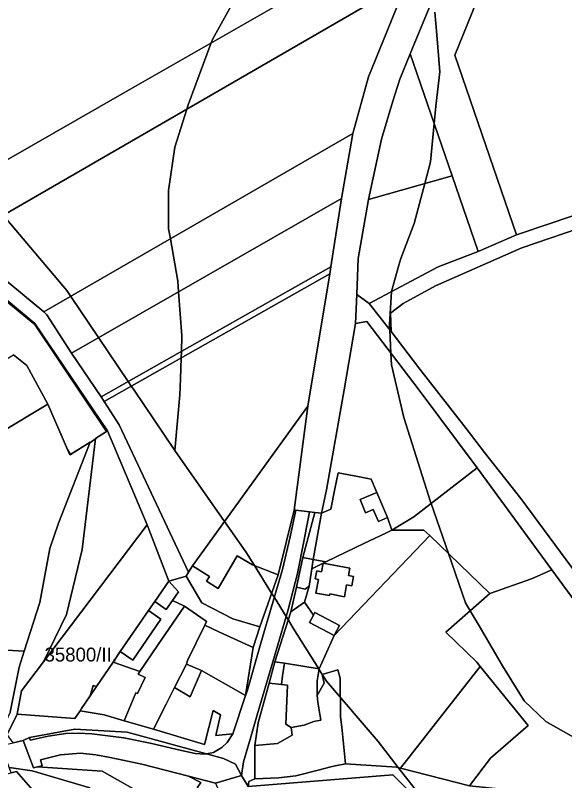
# Model space of a CAD drawing. Extents: x -522079 to -518833, y -1142400 to -1139961.
# Drawn here: x -520469.6 to -520272.1, y -1140796 to -1140520.9 of the extents above; entities that cross this region are included whole.
import ezdxf

# ---------------------------------------------------------------- set-up
doc = ezdxf.new("R2010")
doc.units = 0
for name, color, linetype in [('95560013', 7, 'Continuous'), ('95590013', 7, 'Continuous'), ('95600013', 7, 'Continuous'), ('95610013', 7, 'Continuous'), ('95630013', 7, 'Continuous'), ('95640013', 7, 'Continuous'), ('95660013', 7, 'Continuous')]:
    doc.layers.add(name, color=color, linetype=linetype)

msp = doc.modelspace()

# ---------------------------------------------------------------- linework, layer by layer
at = {"layer": '95560013'}
for points in [[(-520201.76, -1140565.63), (-520263.96, -1140591.19), (-520277.29, -1140595.78), (-520289.45, -1140599.87), (-520311.64, -1140535.23), (-520265.09, -1140420.72), (-520257.35, -1140408.66)], [(-520345.47, -1140414.38), (-520320.44, -1140485.82), (-520431.13, -1140549.18), (-520503.8, -1140590.78), (-520557.7, -1140546.26), (-520562.49, -1140540.48), (-520469.06, -1140486.19)], [(-520490.09, -1140602.11), (-520503.8, -1140590.78), (-520431.13, -1140549.18), (-520320.44, -1140485.82), (-520319.85, -1140487.51), (-520328.73, -1140508.82)], [(-520459.31, -1140627.54), (-520490.09, -1140602.11), (-520328.73, -1140508.82), (-520342.62, -1140543.01), (-520348.21, -1140563.43)], [(-520334.77, -1140627.95), (-520330.21, -1140624.54), (-520318.61, -1140618.22), (-520287.56, -1140604.5), (-520262.2, -1140595.87), (-520167.57, -1140556.99), (-520135.55, -1140594.91), (-520098.36, -1140648.01), (-520267.51, -1140722.14), (-520287.89, -1140694.59), (-520300.9, -1140678.05), (-520307.57, -1140669.43), (-520324.2, -1140648.06), (-520334.5, -1140634.63)], [(-520449.35, -1140642.33), (-520352.4, -1140586.73), (-520356.14, -1140611.39), (-520438.76, -1140658.07)], [(-520356.14, -1140611.39), (-520356.59, -1140613.91), (-520437.69, -1140659.73), (-520438.76, -1140658.07)], [(-520356.59, -1140613.91), (-520364.42, -1140661.36), (-520405.96, -1140718.81), (-520407.37, -1140721.08), (-520432.32, -1140668.06), (-520437.69, -1140659.73)], [(-520303.74, -1140753.44), (-520314.83, -1140742.62), (-520298.98, -1140728.74), (-520284.03, -1140723.41), (-520276.72, -1140720.19), (-520215.27, -1140803.99), (-520216.9, -1140807.42), (-520249.32, -1140803.75), (-520306.3, -1140797.86), (-520298.77, -1140787.91), (-520285.25, -1140776.21), (-520302.54, -1140754.92)]]:
    msp.add_lwpolyline(points, close=True, dxfattribs=at)
at = {"layer": '95590013'}
for points in [[(-520327.66, -1140534.75), (-520312.59, -1140578.66), (-520342.68, -1140587.14), (-520337.95, -1140565.45), (-520333.94, -1140551.84), (-520331.42, -1140543.88)], [(-520449.35, -1140642.33), (-520458.26, -1140628.64), (-520459.31, -1140627.54), (-520348.21, -1140563.43), (-520352.4, -1140586.73)], [(-520342.68, -1140587.14), (-520312.59, -1140578.66), (-520303.27, -1140605.8), (-520317.54, -1140611.38), (-520342.44, -1140624.55), (-520346.89, -1140621.24), (-520346.39, -1140608.35)], [(-520359.48, -1140699.91), (-520357.72, -1140691.49), (-520351.39, -1140655.57), (-520347.36, -1140631.75), (-520343.28, -1140631.04), (-520324.4, -1140655.71), (-520303.56, -1140683.6), (-520326.31, -1140701.14), (-520334.3, -1140706.02), (-520335.84, -1140701.48), (-520339.66, -1140692.44), (-520341.7, -1140687.61), (-520345.87, -1140686.81), (-520353.6, -1140685.32), (-520354.71, -1140691.1), (-520356.12, -1140698.44)], [(-520375.15, -1140722.06), (-520384.29, -1140718.48), (-520389.9, -1140715.22), (-520396.68, -1140726.94), (-520400.9, -1140724.3), (-520399.85, -1140722.62), (-520405.96, -1140718.81), (-520364.42, -1140661.36), (-520369.41, -1140698.76)], [(-520459.41, -1140753.25), (-520451.15, -1140736.24), (-520445.6, -1140712.87), (-520440.71, -1140673.04), (-520436.48, -1140670.33), (-520422.23, -1140704.1)], [(-520276.72, -1140720.19), (-520284.03, -1140723.41), (-520298.98, -1140728.74), (-520320.58, -1140707.95), (-520322.69, -1140705.99), (-520334.3, -1140706.02), (-520326.31, -1140701.14), (-520303.56, -1140683.6)], [(-520445.76, -1140770.03), (-520446.34, -1140770.88), (-520448.2, -1140773.61), (-520468.98, -1140772.14), (-520467.31, -1140763.69), (-520459.41, -1140753.25), (-520422.23, -1140704.1), (-520414.39, -1140724.32), (-520419.44, -1140731.56), (-520421.72, -1140734.81), (-520431.9, -1140749.57), (-520434.44, -1140753.41), (-520440.36, -1140762.11), (-520441.56, -1140761.77), (-520442.66, -1140765.49)], [(-520322.69, -1140705.99), (-520320.58, -1140707.95), (-520354.98, -1140743.86), (-520353.05, -1140740.25), (-520361.88, -1140735.57), (-520362.41, -1140736.49), (-520365.68, -1140731.9), (-520364.02, -1140726.04), (-520363.02, -1140719.82), (-520358.95, -1140717.87), (-520357.97, -1140717.4), (-520347.29, -1140712.26), (-520344.29, -1140710.82), (-520336.43, -1140707.04), (-520334.3, -1140706.02)], [(-520331.09, -1140791.46), (-520332.51, -1140791.1), (-520350.89, -1140789.92), (-520352.17, -1140776.77), (-520352.71, -1140773.02), (-520352.78, -1140759.2), (-520353.64, -1140756.21), (-520359.31, -1140757.88), (-520358.59, -1140760.98), (-520361.04, -1140765.41), (-520361.11, -1140760.14), (-520360.42, -1140755.8), (-520354.98, -1140743.86), (-520320.58, -1140707.95), (-520298.98, -1140728.74), (-520314.83, -1140742.62), (-520303.74, -1140753.44), (-520302.54, -1140754.92)], [(-520358.95, -1140717.87), (-520359.53, -1140720.91), (-520361.21, -1140720.62), (-520361.8, -1140723.5), (-520360.67, -1140723.75), (-520361.57, -1140728.6), (-520356.67, -1140729.48), (-520356.58, -1140728.88), (-520351.32, -1140729.89), (-520350.51, -1140725.65), (-520348.59, -1140726.01), (-520347.97, -1140722.63), (-520349.88, -1140722.27), (-520349.37, -1140719.63)], [(-520302.54, -1140754.92), (-520285.25, -1140776.21), (-520298.77, -1140787.91), (-520306.3, -1140797.86), (-520331.09, -1140791.46)], [(-520375.33, -1140782.59), (-520383.46, -1140783.32), (-520382.29, -1140775.26), (-520378.38, -1140760.91), (-520373.94, -1140761.39), (-520371.72, -1140761.64), (-520372.32, -1140775.75), (-520370.42, -1140776.86), (-520370.11, -1140779.64)]]:
    msp.add_lwpolyline(points, close=True, dxfattribs=at)
at = {"layer": '95600013'}
msp.add_lwpolyline([(-520482.03, -1140698.6), (-520492.24, -1140681.28), (-520457.96, -1140660.67), (-520449.96, -1140678.96), (-520442.74, -1140674.34), (-520454.03, -1140703.46), (-520457.2, -1140712.56), (-520460.77, -1140732), (-520466.36, -1140749.44), (-520479.24, -1140748.79), (-520495.27, -1140747.98), (-520489.4, -1140725.83), (-520488.36, -1140721.89)], close=True, dxfattribs=at)
at = {"layer": '95610013'}
msp.add_lwpolyline([(-520265.09, -1140420.72), (-520311.64, -1140535.23), (-520289.45, -1140599.87), (-520303.27, -1140605.8), (-520312.59, -1140578.66), (-520327.66, -1140534.75), (-520307.77, -1140486.46)], dxfattribs=at)
msp.add_lwpolyline([(-520553.91, -1140708.56), (-520579.53, -1140724.2), (-520579.01, -1140725.05), (-520580.64, -1140725.97), (-520586.97, -1140713.22), (-520470.21, -1140643.01), (-520465.4, -1140646.75), (-520457.96, -1140660.67), (-520492.24, -1140681.28), (-520531.99, -1140705.14), (-520549.51, -1140715.7), (-520553.39, -1140709.41)], close=True, dxfattribs=at)
at = {"layer": '95630013'}
for points in [[(-520560.63, -1140549.81), (-520462.54, -1140631.68), (-520436.48, -1140670.33), (-520440.71, -1140673.04), (-520445.6, -1140712.87), (-520451.15, -1140736.24), (-520459.41, -1140753.25), (-520467.31, -1140763.69), (-520468.98, -1140772.14), (-520472.47, -1140779.4)], [(-520471.47, -1140771.35), (-520468.2, -1140755.18), (-520466.36, -1140749.44), (-520460.77, -1140732), (-520457.2, -1140712.56), (-520454.03, -1140703.46), (-520442.74, -1140674.34), (-520449.96, -1140678.96), (-520457.96, -1140660.67), (-520465.4, -1140646.75), (-520470.21, -1140643.01)], [(-520462.48, -1140800.42), (-520469.2, -1140792.72), (-520471.14, -1140793.15), (-520474.64, -1140783.36), (-520470.41, -1140782.37), (-520466.78, -1140781.53), (-520463.08, -1140791.37), (-520461.64, -1140791.05), (-520438.34, -1140792.64), (-520421.04, -1140802.37)], [(-520397.69, -1140796.9), (-520388.29, -1140794.2), (-520385.85, -1140798.14)], [(-520385.85, -1140798.14), (-520333.88, -1140793.93), (-520323.97, -1140803.87)]]:
    msp.add_lwpolyline(points, dxfattribs=at)
at = {"layer": '95640013'}
for points in [[(-519947.24, -1140466.47), (-520104.66, -1140531.14), (-520155.91, -1140552.2), (-520167.57, -1140556.99), (-520262.2, -1140595.87), (-520287.56, -1140604.5), (-520318.61, -1140618.22), (-520330.21, -1140624.54), (-520334.77, -1140627.95), (-520334.5, -1140634.63), (-520342.44, -1140624.55), (-520317.54, -1140611.38), (-520303.27, -1140605.8), (-520289.45, -1140599.87), (-520277.29, -1140595.78), (-520263.96, -1140591.19), (-520201.76, -1140565.63), (-520182.86, -1140557.87), (-520106.55, -1140526.52), (-520084.71, -1140517.54), (-520041.44, -1140499.76), (-520031.39, -1140495.83), (-519949.02, -1140461.79)], [(-520307.77, -1140486.46), (-520327.66, -1140534.75), (-520331.42, -1140543.88), (-520333.94, -1140551.84), (-520337.95, -1140565.45), (-520342.68, -1140587.14), (-520346.39, -1140608.35), (-520346.89, -1140621.24), (-520347.36, -1140631.75), (-520351.39, -1140655.57), (-520357.72, -1140691.49), (-520359.48, -1140699.91), (-520361.97, -1140699.61), (-520363.79, -1140699.4), (-520368.79, -1140698.83), (-520369.41, -1140698.76), (-520364.42, -1140661.36), (-520356.59, -1140613.91), (-520356.14, -1140611.39), (-520352.4, -1140586.73), (-520348.21, -1140563.43), (-520342.62, -1140543.01), (-520328.73, -1140508.82)], [(-520587.65, -1140510.13), (-520562.49, -1140540.48), (-520557.7, -1140546.26), (-520503.8, -1140590.78), (-520490.09, -1140602.11), (-520459.31, -1140627.54), (-520458.26, -1140628.64), (-520449.35, -1140642.33), (-520438.76, -1140658.07), (-520437.69, -1140659.73), (-520432.32, -1140668.06), (-520407.37, -1140721.08), (-520408.23, -1140722.45), (-520414.39, -1140724.32), (-520422.23, -1140704.1), (-520436.48, -1140670.33), (-520462.54, -1140631.68), (-520560.63, -1140549.81), (-520611.7, -1140490.5)], [(-520215.27, -1140803.99), (-520276.72, -1140720.19), (-520303.56, -1140683.6), (-520324.4, -1140655.71), (-520343.28, -1140631.04), (-520347.36, -1140631.75), (-520346.89, -1140621.24), (-520342.44, -1140624.55), (-520334.5, -1140634.63), (-520324.2, -1140648.06), (-520307.57, -1140669.43), (-520300.9, -1140678.05), (-520287.89, -1140694.59), (-520267.51, -1140722.14), (-520249.86, -1140745.99), (-520216.26, -1140791.5), (-520210.31, -1140799.64)]]:
    msp.add_lwpolyline(points, dxfattribs=at)
for points in [[(-520343.7, -1140699.72), (-520340.94, -1140698.56), (-520339.07, -1140702.89), (-520335.84, -1140701.48), (-520334.3, -1140706.02), (-520336.43, -1140707.04), (-520344.29, -1140710.82), (-520347.29, -1140712.26), (-520357.97, -1140717.4), (-520362.54, -1140716.5), (-520359.48, -1140699.91), (-520356.12, -1140698.44), (-520354.71, -1140691.1), (-520353.6, -1140685.32), (-520345.87, -1140686.81), (-520341.7, -1140687.61), (-520339.66, -1140692.44), (-520345.67, -1140694.97)], [(-520335.84, -1140701.48), (-520339.07, -1140702.89), (-520340.94, -1140698.56), (-520343.7, -1140699.72), (-520345.67, -1140694.97), (-520339.66, -1140692.44)], [(-520386.83, -1140765.41), (-520384.05, -1140748.14), (-520381.74, -1140740.77), (-520375.15, -1140722.06), (-520369.41, -1140698.76), (-520368.79, -1140698.83), (-520370.77, -1140708.37), (-520373.52, -1140720.12), (-520380.21, -1140742.93), (-520381.78, -1140748.3), (-520386.29, -1140763.79)], [(-520394.79, -1140788), (-520400.82, -1140786.35), (-520398.38, -1140785.83), (-520395.36, -1140784.1), (-520393.48, -1140782.23), (-520391.38, -1140779.15), (-520386.83, -1140765.41), (-520386.29, -1140763.79), (-520381.78, -1140748.3), (-520380.21, -1140742.93), (-520373.52, -1140720.12), (-520370.77, -1140708.37), (-520368.79, -1140698.83), (-520363.79, -1140699.4), (-520365.84, -1140710.09), (-520368.19, -1140721.56), (-520371.69, -1140734.94), (-520377.6, -1140755.34), (-520382.64, -1140772.35), (-520385.08, -1140780.78), (-520387.56, -1140789.2), (-520388.29, -1140794.2), (-520390.4, -1140790.05)], [(-520383.46, -1140783.32), (-520383.53, -1140795.4), (-520385.62, -1140796.31), (-520385.85, -1140798.14), (-520388.29, -1140794.2), (-520387.56, -1140789.2), (-520385.08, -1140780.78), (-520382.64, -1140772.35), (-520377.6, -1140755.34), (-520371.69, -1140734.94), (-520368.19, -1140721.56), (-520365.84, -1140710.09), (-520363.79, -1140699.4), (-520361.97, -1140699.61), (-520366.26, -1140715.78), (-520368.57, -1140726.47), (-520370.5, -1140735.37), (-520376.29, -1140753.27), (-520378.38, -1140760.91), (-520382.29, -1140775.26)], [(-520366.26, -1140715.78), (-520361.97, -1140699.61), (-520359.48, -1140699.91), (-520362.54, -1140716.5)], [(-520381.74, -1140740.77), (-520391.43, -1140737.8), (-520402.49, -1140732.06), (-520404.15, -1140729.51), (-520408.23, -1140722.45), (-520407.37, -1140721.08), (-520405.96, -1140718.81), (-520399.85, -1140722.62), (-520400.9, -1140724.3), (-520396.68, -1140726.94), (-520389.9, -1140715.22), (-520384.29, -1140718.48), (-520375.15, -1140722.06)], [(-520368.57, -1140726.47), (-520366.26, -1140715.78), (-520362.54, -1140716.5), (-520363.02, -1140719.82), (-520364.02, -1140726.04), (-520365.37, -1140727.18)], [(-520357.97, -1140717.4), (-520358.95, -1140717.87), (-520363.02, -1140719.82), (-520362.54, -1140716.5)], [(-520358.95, -1140717.87), (-520349.37, -1140719.63), (-520349.88, -1140722.27), (-520347.97, -1140722.63), (-520348.59, -1140726.01), (-520350.51, -1140725.65), (-520351.32, -1140729.89), (-520356.58, -1140728.88), (-520356.67, -1140729.48), (-520361.57, -1140728.6), (-520360.67, -1140723.75), (-520361.8, -1140723.5), (-520361.21, -1140720.62), (-520359.53, -1140720.91)], [(-520408.83, -1140733.26), (-520413.15, -1140731.24), (-520410.99, -1140728.16), (-520414.39, -1140724.32), (-520408.23, -1140722.45), (-520404.15, -1140729.51), (-520402.49, -1140732.06), (-520391.43, -1140737.8), (-520381.74, -1140740.77), (-520384.05, -1140748.14), (-520390.88, -1140745.01), (-520396.18, -1140742.58), (-520401.52, -1140740.13), (-520400.87, -1140738.78), (-520401.38, -1140738.43)], [(-520415.38, -1140734.43), (-520419.44, -1140731.56), (-520414.39, -1140724.32), (-520410.99, -1140728.16), (-520413.15, -1140731.24)], [(-520365.37, -1140727.18), (-520364.02, -1140726.04), (-520365.68, -1140731.9), (-520370.5, -1140735.37), (-520368.57, -1140726.47)], [(-520413.15, -1140731.24), (-520408.83, -1140733.26), (-520418.47, -1140747.39), (-520424.83, -1140756.78), (-520434.44, -1140753.41), (-520431.9, -1140749.57), (-520427.38, -1140752.69), (-520417.23, -1140737.96), (-520421.72, -1140734.81), (-520419.44, -1140731.56), (-520415.38, -1140734.43)], [(-520407.68, -1140752.84), (-520408.04, -1140754.09), (-520412.32, -1140762.52), (-520415.37, -1140768.55), (-520419.92, -1140777.53), (-520430.49, -1140774.45), (-520426.25, -1140764.44), (-520425.69, -1140764.63), (-520422.94, -1140758.87), (-520425.43, -1140757.74), (-520424.83, -1140756.78), (-520418.47, -1140747.39), (-520408.83, -1140733.26), (-520401.38, -1140738.43), (-520400.87, -1140738.78), (-520401.52, -1140740.13)], [(-520365.68, -1140731.9), (-520362.41, -1140736.49), (-520363.84, -1140739.14), (-520354.98, -1140743.86), (-520360.42, -1140755.8), (-520372.89, -1140753.81), (-520376.29, -1140753.27), (-520370.5, -1140735.37)], [(-520427.38, -1140752.69), (-520431.9, -1140749.57), (-520421.72, -1140734.81), (-520417.23, -1140737.96)], [(-520361.88, -1140735.57), (-520353.05, -1140740.25), (-520354.98, -1140743.86), (-520363.84, -1140739.14), (-520362.41, -1140736.49)], [(-520386.83, -1140765.41), (-520402.66, -1140756.46), (-520408.04, -1140754.09), (-520407.68, -1140752.84), (-520401.52, -1140740.13), (-520396.18, -1140742.58), (-520390.88, -1140745.01), (-520384.05, -1140748.14)], [(-520480.98, -1140785.01), (-520484.92, -1140786.1), (-520485.38, -1140782.23), (-520498.09, -1140783.57), (-520499.08, -1140774.22), (-520498.32, -1140766.26), (-520497.66, -1140759.42), (-520497.51, -1140757.87), (-520496.94, -1140755.37), (-520495.27, -1140747.98), (-520479.24, -1140748.79), (-520466.36, -1140749.44), (-520468.2, -1140755.18), (-520471.47, -1140771.35), (-520475.64, -1140780.08), (-520474.64, -1140783.36)], [(-520434.44, -1140753.41), (-520424.83, -1140756.78), (-520425.43, -1140757.74), (-520422.94, -1140758.87), (-520425.69, -1140764.63), (-520426.25, -1140764.44), (-520430.49, -1140774.45), (-520437.68, -1140772.4), (-520446.34, -1140770.88), (-520445.76, -1140770.03), (-520442.66, -1140765.49), (-520440.36, -1140762.11)], [(-520372.89, -1140753.81), (-520373.51, -1140758.29), (-520373.94, -1140761.39), (-520378.38, -1140760.91), (-520376.29, -1140753.27)], [(-520419.92, -1140777.53), (-520415.37, -1140768.55), (-520412.32, -1140762.52), (-520406.78, -1140765.84), (-520402.66, -1140756.46), (-520386.83, -1140765.41), (-520391.38, -1140779.15), (-520397.56, -1140779.72), (-520395.82, -1140772.4), (-520398.45, -1140770.83), (-520401.54, -1140783.02)], [(-520412.32, -1140762.52), (-520408.04, -1140754.09), (-520402.66, -1140756.46), (-520406.78, -1140765.84)], [(-520361.04, -1140765.41), (-520358.59, -1140760.98), (-520359.31, -1140757.88), (-520353.64, -1140756.21), (-520352.78, -1140759.2), (-520352.71, -1140773.02), (-520352.17, -1140776.77), (-520350.89, -1140789.92), (-520354.62, -1140790.65), (-520356.2, -1140791.03), (-520360.72, -1140792.17), (-520368.73, -1140794.29), (-520374.96, -1140794.94), (-520383.53, -1140795.4), (-520383.46, -1140783.32), (-520375.33, -1140782.59), (-520370.11, -1140779.64), (-520370.42, -1140776.86), (-520365.71, -1140776.1), (-520362.27, -1140774.68), (-520359.77, -1140774.23), (-520360.88, -1140767.78)], [(-520361.04, -1140765.41), (-520360.88, -1140767.78), (-520359.77, -1140774.23), (-520362.27, -1140774.68), (-520365.71, -1140776.1), (-520370.42, -1140776.86), (-520372.32, -1140775.75), (-520371.72, -1140761.64), (-520373.94, -1140761.39), (-520373.51, -1140758.29), (-520372.89, -1140753.81), (-520360.42, -1140755.8), (-520361.11, -1140760.14)], [(-520440.36, -1140762.11), (-520442.66, -1140765.49), (-520441.56, -1140761.77)], [(-520470.41, -1140782.37), (-520472.47, -1140779.4), (-520468.98, -1140772.14), (-520448.2, -1140773.61), (-520446.34, -1140770.88), (-520437.68, -1140772.4), (-520430.49, -1140774.45), (-520419.92, -1140777.53), (-520401.54, -1140783.02), (-520398.45, -1140770.83), (-520395.82, -1140772.4), (-520397.56, -1140779.72), (-520391.38, -1140779.15), (-520393.48, -1140782.23), (-520395.36, -1140784.1), (-520398.38, -1140785.83), (-520400.82, -1140786.35), (-520429.44, -1140778.54), (-520448.23, -1140777.51), (-520464.48, -1140780.47), (-520466.78, -1140781.53)], [(-520400.82, -1140786.35), (-520401.42, -1140786.48), (-520404.95, -1140786.22), (-520409.82, -1140785.14), (-520421.16, -1140782.56), (-520430.59, -1140780.58), (-520442.14, -1140779.17), (-520447.03, -1140778.94), (-520451.46, -1140779.1), (-520457.74, -1140780.06), (-520464.21, -1140781.48), (-520464.48, -1140780.47), (-520448.23, -1140777.51), (-520429.44, -1140778.54)], [(-520407.29, -1140794.34), (-520424.08, -1140790.09), (-520435.45, -1140787.73), (-520440.68, -1140786.74), (-520446.22, -1140786.13), (-520453.31, -1140786.74), (-520460.51, -1140788.53), (-520459.9, -1140790.65), (-520461.64, -1140791.05), (-520463.08, -1140791.37), (-520466.78, -1140781.53), (-520464.48, -1140780.47), (-520464.21, -1140781.48), (-520457.74, -1140780.06), (-520451.46, -1140779.1), (-520447.03, -1140778.94), (-520442.14, -1140779.17), (-520430.59, -1140780.58), (-520421.16, -1140782.56), (-520409.82, -1140785.14), (-520404.95, -1140786.22), (-520401.42, -1140786.48), (-520400.82, -1140786.35), (-520394.79, -1140788), (-520390.4, -1140790.05), (-520388.29, -1140794.2), (-520397.69, -1140796.9)], [(-520461.64, -1140791.05), (-520459.9, -1140790.65), (-520460.51, -1140788.53), (-520453.31, -1140786.74), (-520446.22, -1140786.13), (-520440.68, -1140786.74), (-520435.45, -1140787.73), (-520424.08, -1140790.09), (-520407.29, -1140794.34), (-520402.86, -1140796.64), (-520404.19, -1140798.55), (-520401.05, -1140800.99), (-520400.31, -1140802.09), (-520404.93, -1140803.86), (-520413.92, -1140809.23), (-520421.04, -1140802.37), (-520438.34, -1140792.64)], [(-520332.51, -1140791.1), (-520331.09, -1140791.46), (-520306.3, -1140797.86), (-520249.32, -1140803.75), (-520216.9, -1140807.42), (-520204.62, -1140815.75), (-520252.34, -1140811), (-520251.92, -1140810), (-520288.38, -1140807.41), (-520323.97, -1140803.87), (-520333.88, -1140793.93), (-520385.85, -1140798.14), (-520385.62, -1140796.31), (-520383.53, -1140795.4), (-520374.96, -1140794.94), (-520368.73, -1140794.29), (-520360.72, -1140792.17), (-520356.2, -1140791.03), (-520354.62, -1140790.65), (-520350.89, -1140789.92)], [(-520479.52, -1140802.35), (-520481.31, -1140802.54), (-520492.42, -1140803.71), (-520483.65, -1140796.14), (-520478.64, -1140794.97), (-520477.5, -1140794.69), (-520471.14, -1140793.15), (-520469.2, -1140792.72), (-520462.48, -1140800.42), (-520444.45, -1140805.57), (-520456.93, -1140810.9), (-520471.87, -1140801.78), (-520475.9, -1140802.08)], [(-520402.86, -1140796.64), (-520407.29, -1140794.34), (-520397.69, -1140796.9), (-520396.18, -1140800.22), (-520397.88, -1140801.13), (-520400.31, -1140802.09), (-520401.05, -1140800.99), (-520404.19, -1140798.55)]]:
    msp.add_lwpolyline(points, close=True, dxfattribs=at)
at = {"layer": '95660013'}
for points in [[(-520391.98, -1140517.59), (-520398.63, -1140529.45), (-520399.16, -1140530.88), (-520407.49, -1140553.17), (-520407.95, -1140554.63), (-520412.29, -1140568.36), (-520414.51, -1140583.92), (-520414.51, -1140597.63), (-520413.86, -1140601.32), (-520411.19, -1140616.53), (-520411.05, -1140618.35), (-520410.9, -1140620.28), (-520409.71, -1140636.17), (-520409.9, -1140641.76), (-520409.98, -1140644.08), (-520410.25, -1140651.6), (-520410.45, -1140657.29), (-520411.31, -1140666.69), (-520412.29, -1140677.3), (-520427.16, -1140655.28), (-520427.9, -1140654.19), (-520429, -1140652.56), (-520439.66, -1140636.77), (-520449.66, -1140621.97), (-520451.08, -1140619.87), (-520473.9, -1140592.75)], [(-520323.76, -1140801.76), (-520331.96, -1140791.24), (-520339.2, -1140781.94), (-520357.72, -1140760.26), (-520360.44, -1140755.92), (-520360.52, -1140755.78), (-520369.67, -1140741.14), (-520371.45, -1140738.29), (-520372.28, -1140736.96), (-520376.48, -1140730.23), (-520377.47, -1140728.65), (-520383.67, -1140718.72), (-520386.74, -1140713.8), (-520394.42, -1140702.84), (-520412.29, -1140677.3), (-520411.31, -1140666.69), (-520410.45, -1140657.29), (-520410.25, -1140651.6), (-520409.98, -1140644.08), (-520409.9, -1140641.76), (-520409.71, -1140636.17), (-520410.9, -1140620.28), (-520411.05, -1140618.35), (-520411.19, -1140616.53), (-520413.86, -1140601.32), (-520414.51, -1140597.63), (-520414.51, -1140583.92), (-520412.29, -1140568.36), (-520407.95, -1140554.63), (-520407.49, -1140553.17), (-520399.16, -1140530.88), (-520398.63, -1140529.45), (-520391.98, -1140517.59)], [(-520318.84, -1140519.82), (-520318.1, -1140527.97), (-520316.99, -1140541.31), (-520318.47, -1140553.54), (-520319.05, -1140559.83), (-520320.32, -1140573.55), (-520322.41, -1140581.43), (-520326.23, -1140595.78), (-520331.03, -1140608.38), (-520331.69, -1140610.75), (-520334.35, -1140620.26), (-520335.09, -1140632.09), (-520334.99, -1140634), (-520334.56, -1140642.43), (-520334.35, -1140646.54), (-520329.92, -1140665.44), (-520320.31, -1140695.83), (-520320.13, -1140696.37), (-520313.9, -1140714.38), (-520307.76, -1140732.14), (-520306.09, -1140734.97), (-520302.9, -1140740.4), (-520294.46, -1140754.75), (-520286.7, -1140767.34), (-520278.94, -1140774.76), (-520268.97, -1140780.31)], [(-520268.97, -1140780.31), (-520278.94, -1140774.76), (-520286.7, -1140767.34), (-520294.46, -1140754.75), (-520302.9, -1140740.4), (-520306.09, -1140734.97), (-520307.76, -1140732.14), (-520313.9, -1140714.38), (-520320.13, -1140696.37), (-520320.31, -1140695.83), (-520329.92, -1140665.44), (-520334.35, -1140646.54), (-520334.56, -1140642.43), (-520334.99, -1140634), (-520335.09, -1140632.09), (-520334.35, -1140620.26), (-520331.69, -1140610.75), (-520331.03, -1140608.38), (-520326.23, -1140595.78), (-520322.41, -1140581.43), (-520320.32, -1140573.55), (-520319.05, -1140559.83), (-520318.47, -1140553.54), (-520316.99, -1140541.31), (-520318.1, -1140527.97), (-520318.84, -1140519.82)], [(-520562.29, -1140550.47), (-520462.62, -1140632.02), (-520444.58, -1140658.9), (-520436.78, -1140670.52), (-520440.71, -1140673.04), (-520440.72, -1140673.16), (-520440.84, -1140673.23), (-520441.08, -1140673.37), (-520442.82, -1140674.54), (-520442.74, -1140674.34), (-520449.76, -1140678.83), (-520450.83, -1140676.96), (-520457.96, -1140660.67), (-520465.4, -1140646.75), (-520470.21, -1140643.01)], [(-520470.21, -1140643.01), (-520465.4, -1140646.75), (-520457.96, -1140660.67), (-520450.83, -1140676.96), (-520449.76, -1140678.83), (-520442.74, -1140674.34), (-520442.82, -1140674.54), (-520441.08, -1140673.37), (-520440.84, -1140673.23), (-520440.72, -1140673.16), (-520440.71, -1140673.04), (-520436.78, -1140670.52), (-520444.58, -1140658.9), (-520462.62, -1140632.02), (-520562.29, -1140550.47)], [(-520473.9, -1140592.75), (-520451.08, -1140619.87), (-520449.66, -1140621.97), (-520439.66, -1140636.77), (-520429, -1140652.56), (-520427.9, -1140654.19), (-520427.16, -1140655.28), (-520412.29, -1140677.3), (-520394.42, -1140702.84), (-520386.74, -1140713.8), (-520383.67, -1140718.72), (-520377.47, -1140728.65), (-520376.48, -1140730.23), (-520372.28, -1140736.96), (-520371.45, -1140738.29), (-520369.67, -1140741.14), (-520360.52, -1140755.78), (-520360.44, -1140755.92), (-520357.72, -1140760.26), (-520339.2, -1140781.94), (-520331.96, -1140791.24), (-520323.76, -1140801.76)], [(-520442.83, -1140798.57), (-520463.48, -1140792.48), (-520471.79, -1140791.32)], [(-520471.79, -1140791.32), (-520463.48, -1140792.48), (-520442.83, -1140798.57)]]:
    msp.add_lwpolyline(points, dxfattribs=at)

# ---------------------------------------------------------------- texts
msp.add_text('35800/II.', height=5, rotation=0, dxfattribs=at).set_placement((-520459.09, -1140753.19))

doc.saveas('drawing.dxf')
